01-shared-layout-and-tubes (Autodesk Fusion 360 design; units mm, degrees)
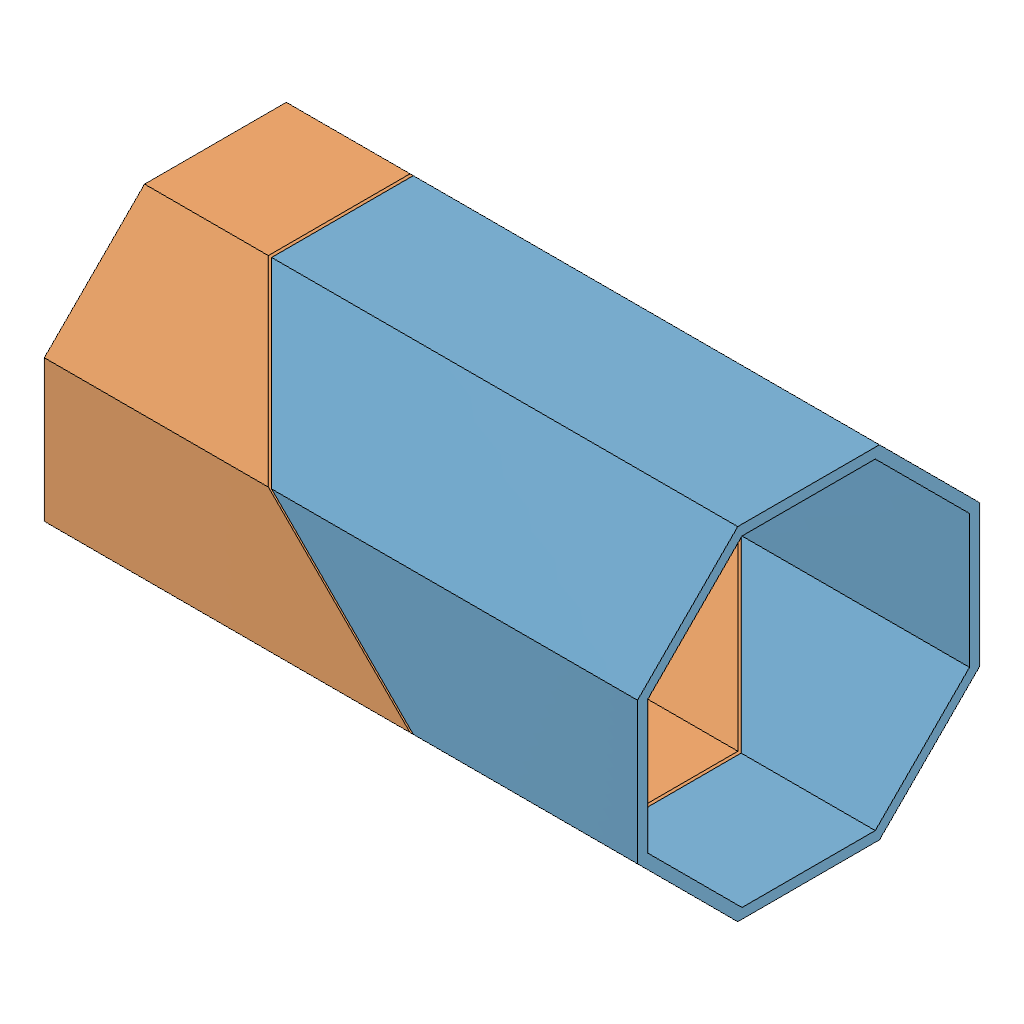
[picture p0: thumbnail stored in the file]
part number: 2026-11-02-20-17-55-344
part number: 2026-11-02-20-17-59-218
part number: 2026-11-02-20-17-59-224
parameter "bodyWidth" = 150 comment "Regular octagon across flats; corner diameter is larger."
parameter "bodyLength" = 260 comment "Overall straight length of the shared master blank."
parameter "splitAngle" = 45 comment "Keep this lesson angle at45 degrees."
parameter "faceGap" = 1 comment "Gap between the two printed joint faces."
parameter "wall" = 4.5 comment "Integrated shell and side brace radial thickness."
parameter "faceHalfWidth" = 31.066 (= "bodyWidth * ( sqrt(2) - 1 ) / 2") comment "Half-width of each outer planar facet."
parameter "memberWidth" = 8 comment "Nominal brace and corner chord width in a facet."
parameter "nodeHalfWidth" = 27.066 (= "faceHalfWidth - memberWidth / 2") comment "Chord centerlines measured from facet center."
parameter "jointNodeQ" = 7 comment "First truss skeleton row from the center joint plane."
parameter "endRim" = 10 comment "Uncut axial rim at each distant end."
parameter "endNodeX" = 124 (= "bodyLength / 2 - endRim + memberWidth / 2") comment "Last skeleton row before aperture inset."
parameter "apertureRadius" = 1.5 comment "Rounded internal corners at triangular openings."
parameter "spokeWidth" = 10 comment "Width of each deep bearing bulkhead spoke."
parameter "spokeDepth" = 18 comment "Bulkhead depth normal to the diagonal joint face."
parameter "carrierOD" = 52 comment "Outside of integrated A front bearing carrier."
parameter "rearCarrierClearance" = 46 comment "Internal carrier relief above front bearing shoulder."
parameter "tubeCornerChamfer" = 0.5 comment "Exposed outside octagon corner bevel."
parameter "tubeRimChamfer" = 0.3 comment "End rim and print-contact edge relief."
parameter "cordStation" = 125 (= "bodyLength / 2 - endRim / 2") comment "Load-test cord port center measured along body X."
parameter "bearingOD" = 22 comment "608 measured outside diameter."
parameter "bearingID" = 8 comment "608 bore."
parameter "bearingWidth" = 7 comment "608 width."
parameter "seatAllowance" = 0.2 comment "Trial DIAMETRAL clearance; choose with printed coupon."
parameter "seatDiameter" = 22.2 (= "bearingOD + seatAllowance") comment "Measured fit controls this."
parameter "coreOD" = 44 comment "Bearing holder outer diameter."
parameter "raceRelief" = 19.5 comment "Outer-ring shoulder opening; verify seals."
parameter "frontSeatDepth" = 7.1 comment "0.1 mm outer-ring axial allowance."
parameter "rearSeatDepth" = 7.2 comment "0.2 mm outer-ring axial float."
parameter "shoulder" = 3 comment "Backing behind each bearing seat."
parameter "supportSpacer" = 12 comment "Purchased metal M3 spacer length."
parameter "supportCircle" = 34 comment "Three M3 support bolts."
parameter "supportSpacerOD" = 6 comment "Purchased spacer outside diameter."
parameter "capThickness" = 3 comment "Both printed outer-ring retaining caps."
parameter "m3Clearance" = 3.3 comment "M3 through holes."
parameter "m4Clearance" = 4.3 comment "M4 through holes."
parameter "qFront" = 0.5 (= "faceGap / 2") comment "Front bearing starts at A mating face."
parameter "qFrontBack" = 10.6 (= "qFront + frontSeatDepth + shoulder") comment "End of integrated A holder."
parameter "qRearBase" = 22.6 (= "qFrontBack + supportSpacer") comment "Start of removable rear holder."
parameter "qRearBearing" = 25.6 (= "qRearBase + shoulder") comment "Rear bearing inner end."
parameter "qRearEnd" = 32.8 (= "qRearBearing + rearSeatDepth") comment "Rear holder outer end."
parameter "bearingSpacing" = 25.1 (= "qRearBearing - qFront") comment "Derived support-center spacing, not a bearing rating."
parameter "mountOD" = 76 comment "B mount and F flange outside diameter."
parameter "mountCircle" = 64 comment "Four M4 attachment holes."
parameter "mountOpening" = 50.3 comment "B through opening."
parameter "hubFace" = -23 comment "Metal hub flat mounting face."
parameter "adapterThickness" = 6 comment "F flange and metal compression sleeve length."
parameter "pilotDiameter" = 50 comment "F shallow centering pilot."
parameter "pilotInside" = 34 comment "Clearance around metal hub."
parameter "pilotHeight" = 2 comment "Short pilot only."
parameter "hubHoleSpacing" = 16 comment "Metal Sonic hub square hole spacing."
parameter "sleeveOD" = 8 comment "M4 metal compression sleeves."
parameter "sleeveAllowance" = 0.2 comment "Trial DIAMETRAL sleeve clearance."
parameter "shaftClearance" = 8.5 comment "F clearance hole; not a bearing."
parameter "nutAF" = 7.2 comment "M4 nominal 7 AF nut trial pocket."
parameter "nutDepth" = 4 comment "Open front M4 nut pocket."
parameter "rootRadius" = 1 comment "Hub-to-wall blend."
parameter "entryChamfer" = 0.4 comment "Assembly lead-in."
parameter "bedRelief" = 0.3 comment "Bed-contact edge allowance."
sketch "01 Master Octagon" plane through (0, 0, 0) normal (1, 0, 0) x axis (0, 0, -1)
  line L1 (31.066, 75) -> (75, 31.066)
  line L2 (-31.066, 75) -> (31.066, 75)
  line L3 (-75, 31.066) -> (-31.066, 75)
  line L4 (-75, -31.066) -> (-75, 31.066)
  line L5 (-31.066, -75) -> (-75, -31.066)
  line L6 (31.066, -75) -> (-31.066, -75)
  line L7 (75, -31.066) -> (31.066, -75)
  line L8 (75, 31.066) -> (75, -31.066)
  point P1 (0, 0)
  point P10 (0, 0)
  point P3 (31.066, 75)
  point P8 (31.066, -75)
  coincident P1 P10
  horizontal L2
  dimension "d59" distance P3 P8 = 150 (= "bodyWidth")
extrude "Extrude1" new body sketch "01 Master Octagon" distance 260 (= "bodyLength")
work_plane "WorkPlane1" RotateAngle 45 (= "splitAngle") ExtraOffset 0
split "Split1"
offset_faces "OffsetFaces1" distance -0.5 (= "-faceGap / 2")
offset_faces "OffsetFaces2" distance -0.5 (= "-faceGap / 2")
component_from_bodies "Body->Comp1"
component_from_bodies "Body->Comp2"
shell "Shell1" innerThickness 4.5 (= "wall")
shell "Shell1" innerThickness 4.5 (= "wall")
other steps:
base_feature "Base Feature1" bodies "A Housing print"
base_feature "Base Feature1" bodies "B Moving Body print"
create_component "CreateComponent1"
reparent_decal "ReparentDecal1"
remove_body "RemoveBody1"
create_component "CreateComponent2"
reparent_decal "ReparentDecal2"
remove_body "RemoveBody2"
named bodies: "A Housing print", "B Moving Body print"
